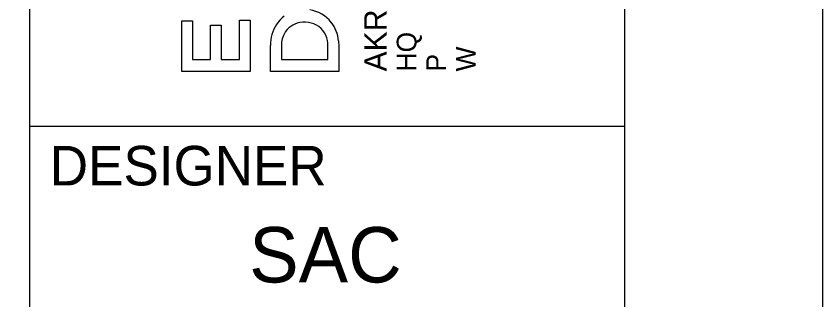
# Model space of a CAD drawing. Extents: x -0.3 to 34, y 0 to 22.
# Drawn here: x 31.965 to 34, y 2.061 to 2.778 of the extents above; entities that cross this region are included whole.
import ezdxf

# ---------------------------------------------------------------- set-up
doc = ezdxf.new("R2010")
doc.units = 0
for name, color, linetype in [('GM_X_Adjacent_County_Text', 7, 'Continuous'), ('GM_X_County', 7, 'Continuous'), ('GM_X_Section', 7, 'Continuous'), ('GM_X_Township', 7, 'Continuous')]:
    doc.layers.add(name, color=color, linetype=linetype)

msp = doc.modelspace()

# ---------------------------------------------------------------- linework, layer by layer
at = {"layer": 'GM_X_Adjacent_County_Text'}
for p, q in [((32.383, 2.6379), (32.383, 2.766)), ((32.383, 2.766), (32.4101, 2.766)), ((32.4101, 2.766), (32.4101, 2.6683)), ((32.455, 2.6683), (32.455, 2.7549)), ((32.455, 2.7549), (32.4822, 2.7549)), ((32.4822, 2.7549), (32.4822, 2.6683)), ((32.5286, 2.6683), (32.5286, 2.7672)), ((32.5286, 2.7672), (32.5557, 2.7672)), ((32.5557, 2.7672), (32.5557, 2.6379)), ((32.6347, 2.7118), (32.6341, 2.7023)), ((32.7785, 2.715), (32.7792, 2.7021)), ((32.6064, 2.638), (32.6064, 2.704)), ((32.6341, 2.7023), (32.6341, 2.6684)), ((32.7515, 2.6683), (32.7515, 2.7024)), ((32.7792, 2.7021), (32.7792, 2.638)), ((32.4101, 2.6683), (32.455, 2.6683)), ((32.4822, 2.6683), (32.5286, 2.6683)), ((32.6341, 2.6684), (32.7515, 2.6683)), ((32.5557, 2.6379), (32.383, 2.6379)), ((32.7792, 2.638), (32.6064, 2.638))]:
    msp.add_line(p, q, dxfattribs=at)
msp.add_lwpolyline([(32.383, 2.6379), (32.383, 2.766), (32.4101, 2.766), (32.4101, 2.6683), (32.455, 2.6683), (32.455, 2.7549), (32.4822, 2.7549), (32.4822, 2.6683), (32.5286, 2.6683), (32.5286, 2.7672), (32.5557, 2.7672), (32.5557, 2.6379)], close=True, dxfattribs=at)
for points in [[(32.7785, 2.715), (32.7792, 2.7021), (32.7792, 2.638), (32.6064, 2.638)], [(32.6347, 2.7118), (32.6341, 2.7023), (32.6341, 2.6684), (32.7515, 2.6683), (32.7515, 2.7024)], [(32.6064, 2.638), (32.6064, 2.704)]]:
    msp.add_lwpolyline(points, dxfattribs=at)
for centre, radius, start, end in [((32.6946, 2.7113), 0.0827, 37.8521, 82.402), ((32.6946, 2.7113), 0.0827, 37.8521, 82.402), ((32.6939, 2.7089), 0.0865, 127.2362, 165.148), ((32.6939, 2.7089), 0.0865, 127.2362, 165.148), ((32.6889, 2.7078), 0.054, 106.1881, 157.3861), ((32.6889, 2.7078), 0.054, 106.1881, 157.3861), ((32.6928, 2.6986), 0.0639, 55.6727, 107.2093), ((32.6928, 2.6986), 0.0639, 55.6727, 107.2093), ((32.6929, 2.705), 0.0587, 357.4662, 52.2665), ((32.6929, 2.705), 0.0587, 357.4662, 52.2665), ((32.6859, 2.7057), 0.0931, 5.7333, 37.304), ((32.6859, 2.7057), 0.0931, 5.7333, 37.304), ((32.7143, 2.7028), 0.1078, 164.7861, 179.3704), ((32.7143, 2.7028), 0.1078, 164.7861, 179.3704), ((32.6983, 2.7039), 0.0641, 157.3571, 172.9275), ((32.6983, 2.7039), 0.0641, 157.3571, 172.9275)]:
    msp.add_arc(centre, radius, start, end, dxfattribs=at)
at = {"layer": 'GM_X_County'}
for p, q in [((32, 0.5), (32, 21.5)), ((32, 2.5), (33.5, 2.5))]:
    msp.add_line(p, q, dxfattribs=at)
msp.add_lwpolyline([(1.5, 21.5), (33.5, 21.5), (33.5, 0.5), (1.5, 0.5)], close=True, dxfattribs=at)
at = {"layer": 'GM_X_Section'}
msp.add_lwpolyline([(0, 0), (34, 0), (34, 22), (0, 22)], close=True, dxfattribs=at)

# ---------------------------------------------------------------- texts
at = {"layer": 'GM_X_Adjacent_County_Text'}
for s, height, p in [('AKRON / CLEVELAND / COLUMBUS', 0.056969, (32.9001, 2.638)), ('HQ ', 0.04985, (32.9749, 2.638)), ('W', 0.0498, (33.1244, 2.638)), ('P', 0.0498, (33.0497, 2.638))]:
    msp.add_text(s, height=height, rotation=90, dxfattribs=at).set_placement(p)
at = {"layer": 'GM_X_Township'}
for s, height, p in [('DESIGNER', 0.1, (32.05, 2.35)), ('SAC', 0.14, (32.5528, 2.105))]:
    msp.add_text(s, height=height, dxfattribs=at).set_placement(p)

doc.saveas('drawing.dxf')
